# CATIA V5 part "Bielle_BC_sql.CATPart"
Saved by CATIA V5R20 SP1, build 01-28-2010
Part number: Bielle BC sql
Publications: "C", "Droite.1", "Droite.2", "Droite.3", "BC", "a"
Bounding box of the stored display mesh (mm): x -20 to 20, y 0 to 0, z 0 to 41
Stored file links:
  C:\Documents and Settings\pschann\Bureau\IAO\Bielle_BC_sql.CATPart
  J:\Projet\CAO\Projet IAO.CATProduct
  C:\Documents and Settings\pschann\Bureau\IAO\Bielle_AB_sql.CATPart
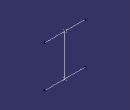
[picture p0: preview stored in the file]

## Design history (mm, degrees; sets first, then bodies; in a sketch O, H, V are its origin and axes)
Parameters
  BC = 41 mm
  a = 12 mm
External parameters (linked from other documents)
  External.AB = 10 mm
Set1
  Point1 "C": type OnPlane, Support yz-plane, RefPoint Point2, H 0, V 41 {= BC}, Direction (0, 1, 0)
  Line1: type PtPt, FirstPoint Point1, SecondPoint Point2
  Line2: type Normal, RefPoint Point1, RefSkin yz-plane, Start -20, End 20
  Line3: type Normal, RefPoint Point2, RefSkin yz-plane, Start -20, End 20
  Point2: type OnPlane, Support yz-plane, H 0, V 0, Direction (0, 1, 0)
Body1 (main body)
Relations
  Point1.V =  (deactivated)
